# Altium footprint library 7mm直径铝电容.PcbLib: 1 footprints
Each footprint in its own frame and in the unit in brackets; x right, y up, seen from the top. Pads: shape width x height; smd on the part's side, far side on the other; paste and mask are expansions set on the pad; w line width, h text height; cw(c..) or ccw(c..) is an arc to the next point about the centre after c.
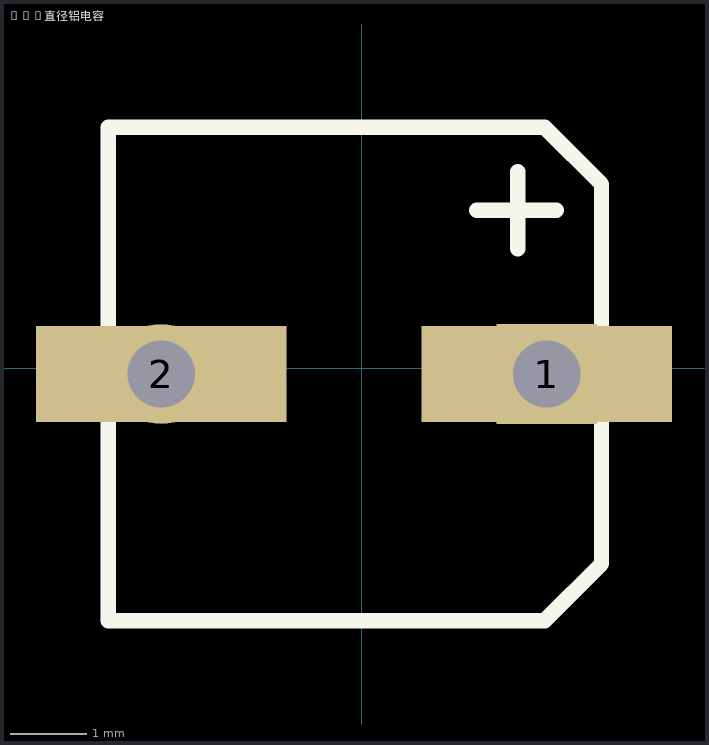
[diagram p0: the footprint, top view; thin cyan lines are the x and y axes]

## 7mm直径铝电容 [mil] "7mm直径铝电容"
pads (4):
  rect 130x50 smd: 1(96,-3) 2(-104,-3)
  rect 52x52 hole 35: 1(96,-3)
  round 52 hole 35: 2(-104,-3)
Top Overlay:
  lines w8: 59.74,82 101,82 ; 81,62 81,102 ; -131.54,-130.95 -131.54,124.95 94.83,124.95 124.36,95.42 124.36,-101.42 94.83,-130.95 -131.54,-130.95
